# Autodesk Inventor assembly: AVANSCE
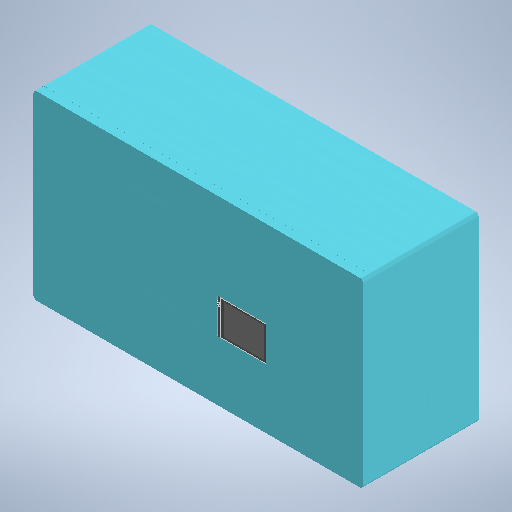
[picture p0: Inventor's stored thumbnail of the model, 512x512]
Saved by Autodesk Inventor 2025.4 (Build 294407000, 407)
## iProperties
Created: 2026-06
Part Number: AVANSCE
Document SubType Name: Assembly
Designer: Marcio Valenzuela
Author: Marcio Valenzuela
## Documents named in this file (10)
- C:\Users\Marcio Valenzuela\OneDrive\Documentos\AVANSCE.iam
- C:\Users\Marcio Valenzuela\OneDrive\Documentos\CARA-MICAELA.ipt
- C:\Users\Marcio Valenzuela\Downloads\tft-lcd-2-4-inch-ili9341-touch-320x240-1.snapshot.15\TFT LCD 2.4 inch ILI9341 touch\TFT LCD 2.4 inch ILI9341 touch\TFT LCD 2.4 inch ILI9341 touch.iam
- C:\Users\Marcio Valenzuela\Downloads\vl53l0x-v2-tof-sensor-1.snapshot.2\vl53l0x\vl53l0x\vl53l0x.ipt
- C:\Users\Marcio Valenzuela\Downloads\seeed-studio-xiao-esp32c3-2.snapshot.2\Seeed-Studio-XIAO-ESP32-C3\Seeed-Studio-XIAO-ESP32-C3\Seeed-Studio-XIAO-ESP32-C3.ipt
- C:\Users\Marcio Valenzuela\Downloads\28byj-48-8.snapshot.5\28BYJ-48\28BYJ-48\28BYJ-48.ipt
- C:\Users\Marcio Valenzuela\OneDrive\Documentos\uln2003_assy.ipt
- C:\Users\Marcio Valenzuela\OneDrive\Documentos\8-ChannelMultiplexer_PCA95.iam
- C:\Users\Marcio Valenzuela\OneDrive\Documentos\BASE-MICAELA.ipt
- C:\Users\Marcio Valenzuela\OneDrive\Documentos\BASE SOPORTE.ipt
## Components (9 placed, 9 different names)
1. CARA-MICAELA:1 — Rotational:1, Rigid:1
2. TFT LCD 2.4 inch ILI9341 touch:1 [sub-assembly] — Rotational:1
3. vl53l0x:1 — Mate:3
4. Seeed-Studio-XIAO-ESP32-C3:1
5. 28BYJ-48:1 — Rotational:2
6. uln2003_assy:1
7. 8-ChannelMultiplexer_PCA95:1 [sub-assembly] — Mate:4
8. BASE-MICAELA:1 — Rotational:2, Rotational:3, Rigid:1
9. BASE SOPORTE:1 — Rotational:3, Mate:1, Mate:2, Mate:3, Mate:4
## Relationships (8: Mate 4, RevoluteJoint 3, WeldJoint 1)
- Rotational:1 [RevoluteJoint]: CARA-MICAELA:1 ↔ TFT LCD 2.4 inch ILI9341 touch:1
- Rotational:2 [RevoluteJoint]: 28BYJ-48:1 ↔ BASE-MICAELA:1
- Rotational:3 [RevoluteJoint]: BASE-MICAELA:1 ↔ BASE SOPORTE:1
- Mate:1: BASE SOPORTE:1
- Mate:2: BASE SOPORTE:1
- Mate:3: vl53l0x:1 ↔ BASE SOPORTE:1
- Mate:4: 8-ChannelMultiplexer_PCA95:1 ↔ BASE SOPORTE:1
- Rigid:1 [WeldJoint]: CARA-MICAELA:1 ↔ BASE-MICAELA:1
